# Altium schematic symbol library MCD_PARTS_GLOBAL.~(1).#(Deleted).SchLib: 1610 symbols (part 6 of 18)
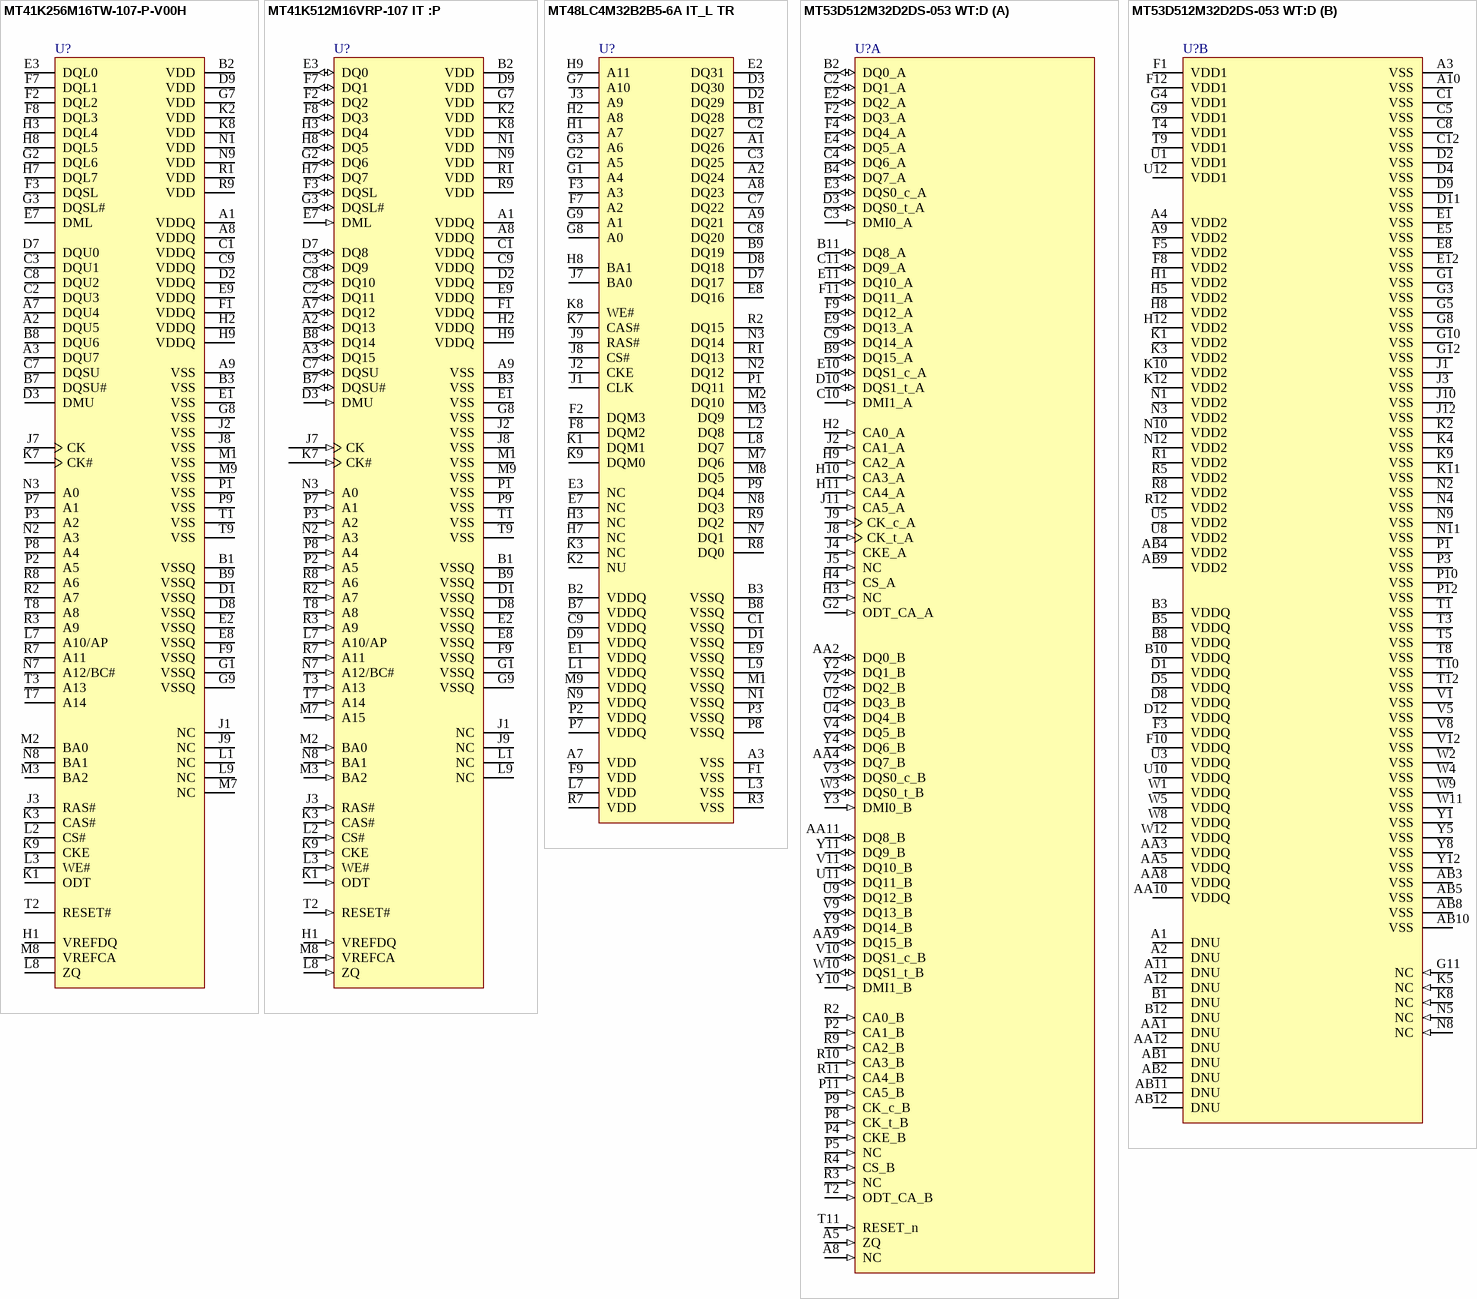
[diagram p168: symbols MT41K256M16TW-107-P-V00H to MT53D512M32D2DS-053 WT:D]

## MT41K512M16VRP-107 IT :P
designator U?
pins: A1 VDDQ "DQ Power Supply: 1.5 V +/- 0.075 V for standard voltage or 1.35V +0.1V, -0.067V for low voltage", A2 DQ13 (io) "Data Input/ Output: Bi-directional data bus.", A3 DQ15 (io) "Data Input/ Output: Bi-directional data bus.", A7 DQ12 (io) "Data Input/ Output: Bi-directional data bus.", A8 VDDQ "DQ Power Supply: 1.5 V +/- 0.075 V for standard voltage or 1.35V +0.1V, -0.067V for low voltage", A9 VSS "Ground", B1 VSSQ "DQ Ground", B2 VDD "Power Supply: 1.5 V +/- 0.075 V for standard voltage or 1.35V +0.1V, -0.067V for low voltage", B3 VSS "Ground", B7 DQSU# (io) "Data Strobe: output with read data, input with write data. Edge-aligned with read data, centered in write data. For the x16, DQSL corresponds to the data on DQL0-DQL7; DQSU corresponds to the data on DQU0-DQU7. The data strobes DQS, DQSL, and DQSU are pa", B8 DQ14 (io) "Data Input/ Output: Bi-directional data bus.", B9 VSSQ "DQ Ground", C1 VDDQ "DQ Power Supply: 1.5 V +/- 0.075 V for standard voltage or 1.35V +0.1V, -0.067V for low voltage", C2 DQ11 (io) "Data Input/ Output: Bi-directional data bus.", C3 DQ9 (io) "Data Input/ Output: Bi-directional data bus.", C7 DQSU (io) "Data Strobe: output with read data, input with write data. Edge-aligned with read data, centered in write data. For the x16, DQSL corresponds to the data on DQL0-DQL7; DQSU corresponds to the data on DQU0-DQU7. The data strobes DQS, DQSL, and DQSU are pa", C8 DQ10 (io) "Data Input/ Output: Bi-directional data bus.", C9 VDDQ "DQ Power Supply: 1.5 V +/- 0.075 V for standard voltage or 1.35V +0.1V, -0.067V for low voltage", D1 VSSQ "DQ Ground", D2 VDDQ "DQ Power Supply: 1.5 V +/- 0.075 V for standard voltage or 1.35V +0.1V, -0.067V for low voltage", D3 DMU (in) "Input Data Mask: DM is an input mask signal for write data. Input data is masked when DM is sampled HIGH coincident with that input data during a Write access. DM is sampled on both edges of DQS. For x8 device, the function of DM or TDQS/TDQS# is enabled", D7 DQ8 (io) "Data Input/ Output: Bi-directional data bus.", D8 VSSQ "DQ Ground", D9 VDD "Power Supply: 1.5 V +/- 0.075 V for standard voltage or 1.35V +0.1V, -0.067V for low voltage", E1 VSS "Ground", E2 VSSQ "DQ Ground", E3 DQ0 (io) "Data Input/ Output: Bi-directional data bus.", E7 DML (in) "Input Data Mask: DM is an input mask signal for write data. Input data is masked when DM is sampled HIGH coincident with that input data during a Write access. DM is sampled on both edges of DQS. For x8 device, the function of DM or TDQS/TDQS# is enabled", E8 VSSQ "DQ Ground", E9 VDDQ "DQ Power Supply: 1.5 V +/- 0.075 V for standard voltage or 1.35V +0.1V, -0.067V for low voltage", F1 VDDQ "DQ Power Supply: 1.5 V +/- 0.075 V for standard voltage or 1.35V +0.1V, -0.067V for low voltage", F2 DQ2 (io) "Data Input/ Output: Bi-directional data bus.", F3 DQSL (io) "Data Strobe: output with read data, input with write data. Edge-aligned with read data, centered in write data. For the x16, DQSL corresponds to the data on DQL0-DQL7; DQSU corresponds to the data on DQU0-DQU7. The data strobes DQS, DQSL, and DQSU are pa", F7 DQ1 (io) "Data Input/ Output: Bi-directional data bus.", F8 DQ3 (io) "Data Input/ Output: Bi-directional data bus.", F9 VSSQ "DQ Ground", G1 VSSQ "DQ Ground", G2 DQ6 (io) "Data Input/ Output: Bi-directional data bus.", G3 DQSL# (io) "Data Strobe: output with read data, input with write data. Edge-aligned with read data, centered in write data. For the x16, DQSL corresponds to the data on DQL0-DQL7; DQSU corresponds to the data on DQU0-DQU7. The data strobes DQS, DQSL, and DQSU are pa", G7 VDD "Power Supply: 1.5 V +/- 0.075 V for standard voltage or 1.35V +0.1V, -0.067V for low voltage", G8 VSS "Ground", G9 VSSQ "DQ Ground", H1 VREFDQ (in) "Reference voltage for DQ", H2 VDDQ "DQ Power Supply: 1.5 V +/- 0.075 V for standard voltage or 1.35V +0.1V, -0.067V for low voltage", H3 DQ4 (io) "Data Input/ Output: Bi-directional data bus.", H7 DQ7 (io) "Data Input/ Output: Bi-directional data bus.", H8 DQ5 (io) "Data Input/ Output: Bi-directional data bus.", H9 VDDQ "DQ Power Supply: 1.5 V +/- 0.075 V for standard voltage or 1.35V +0.1V, -0.067V for low voltage", J1 NC "No Connect: No internal electrical connection is present.", J2 VSS "Ground", J3 RAS# (in) "Command Inputs: RAS#, CAS# and WE# (along with CS#) define the command being entered.", J7 CK (in) "Clock: CK and CK# are differential clock inputs. All address and control input signals are sampled on the crossing of the positive edge of CK and negative edge of CK#.", J8 VSS "Ground", J9 NC "No Connect: No internal electrical connection is present.", K1 ODT (in) "On Die Termination: ODT (registered HIGH) enables termination resistance internal to the DDR3 SDRAM. When enabled, ODT is only applied to each DQ, DQSU, DQSU#, DQSL, DQSL#, DMU, and DML signal. The ODT pin will be ignored if MR1 and MR2 are programmed to", K2 VDD "Power Supply: 1.5 V +/- 0.075 V for standard voltage or 1.35V +0.1V, -0.067V for low voltage", K3 CAS# (in) "Command Inputs: RAS#, CAS# and WE# (along with CS#) define the command being entered.", K7 CK# (in) "Clock: CK and CK# are differential clock inputs. All address and control input signals are sampled on the crossing of the positive edge of CK and negative edge of CK#.", K8 VDD "Power Supply: 1.5 V +/- 0.075 V for standard voltage or 1.35V +0.1V, -0.067V for low voltage", K9 CKE (in) "Clock Enable: CKE HIGH activates, and CKE Low deactivates, internal clock signals and device input buffers and output drivers. Taking CKE Low provides Precharge Power-Down and Self-Refresh operation (all banks idle), or Active Power-Down (row Active in a", L1 NC "No Connect: No internal electrical connection is present.", L2 CS# (in) "Chip Select: All commands are masked when CS# is registered HIGH. CS# provides for external Rank selection on systems with multiple Ranks. CS# is considered part of the command code.", L3 WE# (in) "Command Inputs: RAS#, CAS# and WE# (along with CS#) define the command being entered.", L7 A10/AP (in) "Auto-precharge: A10 is sampled during Read/Write commands to determine whether Autoprecharge should be performed to the accessed bank after the Read/Write operation. (HIGH: Autoprecharge; LOW: no Autoprecharge). A10 is sampled during a Precharge command", L8 ZQ (in) "Reference Pin for ZQ", L9 NC "No Connect: No internal electrical connection is present.", M1 VSS "Ground", M2 BA0 (in) "Bank Address Inputs: BA0 - BA2 define to which bank an Active, Read, Write, or Precharge command is being applied. Bank address also determines which mode register is to be accessed during a MRS cycle.", M3 BA2 (in) "Bank Address Inputs: BA0 - BA2 define to which bank an Active, Read, Write, or Precharge command is being applied. Bank address also determines which mode register is to be accessed during a MRS cycle.", M7 A15 (in) "Address Inputs: Provide the row address for Active commands and the column address for Read/ Write commands to select one location out of the memory array in the respective bank. (A10/AP and A12/BC# have additional functions; see below). The address inpu", M8 VREFCA (in) "Reference voltage for CA", M9 VSS "Ground", N1 VDD "Power Supply: 1.5 V +/- 0.075 V for standard voltage or 1.35V +0.1V, -0.067V for low voltage", N2 A3 (in) "Address Inputs: Provide the row address for Active commands and the column address for Read/ Write commands to select one location out of the memory array in the respective bank. (A10/AP and A12/BC# have additional functions; see below). The address inpu", N3 A0 (in) "Address Inputs: Provide the row address for Active commands and the column address for Read/ Write commands to select one location out of the memory array in the respective bank. (A10/AP and A12/BC# have additional functions; see below). The address inpu", N7 A12/BC# (in) "Burst Chop: A12 / BC# is sampled during Read and Write commands to determine if burst chop (on-the-fly) will be performed. (HIGH, no burst chop; LOW: burst chopped). See command truth table for details.", N8 BA1 (in) "Bank Address Inputs: BA0 - BA2 define to which bank an Active, Read, Write, or Precharge command is being applied. Bank address also determines which mode register is to be accessed during a MRS cycle.", N9 VDD "Power Supply: 1.5 V +/- 0.075 V for standard voltage or 1.35V +0.1V, -0.067V for low voltage", P1 VSS "Ground", P2 A5 (in) "Address Inputs: Provide the row address for Active commands and the column address for Read/ Write commands to select one location out of the memory array in the respective bank. (A10/AP and A12/BC# have additional functions; see below). The address inpu", P3 A2 (in) "Address Inputs: Provide the row address for Active commands and the column address for Read/ Write commands to select one location out of the memory array in the respective bank. (A10/AP and A12/BC# have additional functions; see below). The address inpu", P7 A1 (in) "Address Inputs: Provide the row address for Active commands and the column address for Read/ Write commands to select one location out of the memory array in the respective bank. (A10/AP and A12/BC# have additional functions; see below). The address inpu", P8 A4 (in) "Address Inputs: Provide the row address for Active commands and the column address for Read/ Write commands to select one location out of the memory array in the respective bank. (A10/AP and A12/BC# have additional functions; see below). The address inpu", P9 VSS "Ground", R1 VDD "Power Supply: 1.5 V +/- 0.075 V for standard voltage or 1.35V +0.1V, -0.067V for low voltage", R2 A7 (in) "Address Inputs: Provide the row address for Active commands and the column address for Read/ Write commands to select one location out of the memory array in the respective bank. (A10/AP and A12/BC# have additional functions; see below). The address inpu", R3 A9 (in) "Address Inputs: Provide the row address for Active commands and the column address for Read/ Write commands to select one location out of the memory array in the respective bank. (A10/AP and A12/BC# have additional functions; see below). The address inpu", R7 A11 (in) "Address Inputs: Provide the row address for Active commands and the column address for Read/ Write commands to select one location out of the memory array in the respective bank. (A10/AP and A12/BC# have additional functions; see below). The address inpu", R8 A6 (in) "Address Inputs: Provide the row address for Active commands and the column address for Read/ Write commands to select one location out of the memory array in the respective bank. (A10/AP and A12/BC# have additional functions; see below). The address inpu", R9 VDD "Power Supply: 1.5 V +/- 0.075 V for standard voltage or 1.35V +0.1V, -0.067V for low voltage", T1 VSS "Ground", T2 RESET# (in) "Active Low Asynchronous Reset: Reset is active when RESET# is LOW, and inactive when RESET# is HIGH. RESET# must be HIGH during normal operation. RESET# is a CMOS rail- to-rail signal with DC high and low at 80% and 20% of VDD, i.e., 1.20V for DC high an", T3 A13 (in) "Address Inputs: Provide the row address for Active commands and the column address for Read/ Write commands to select one location out of the memory array in the respective bank. (A10/AP and A12/BC# have additional functions; see below). The address inpu", T7 A14 (in) "Address Inputs: Provide the row address for Active commands and the column address for Read/ Write commands to select one location out of the memory array in the respective bank. (A10/AP and A12/BC# have additional functions; see below). The address inpu", T8 A8 (in) "Address Inputs: Provide the row address for Active commands and the column address for Read/ Write commands to select one location out of the memory array in the respective bank. (A10/AP and A12/BC# have additional functions; see below). The address inpu", T9 VSS "Ground"

## MT48LC4M32B2B5-6A IT_L TR
designator U?
pins: A1 DQ26, A2 DQ24, A3 VSS, A7 VDD, A8 DQ23, A9 DQ21, B1 DQ28, B2 VDDQ, B3 VSSQ, B7 VDDQ, B8 VSSQ, B9 DQ19, C1 VSSQ, C2 DQ27, C3 DQ25, C7 DQ22, C8 DQ20, C9 VDDQ, D1 VSSQ, D2 DQ29, D3 DQ30, D7 DQ17, D8 DQ18, D9 VDDQ, E1 VDDQ, E2 DQ31, E3 NC, E7 NC, E8 DQ16, E9 VSSQ, F1 VSS, F2 DQM3, F3 A3, F7 A2, F8 DQM2, F9 VDD, G1 A4, G2 A5, G3 A6, G7 A10, G8 A0, G9 A1, H1 A7, H2 A8, H3 NC, H7 NC, H8 BA1, H9 A11, J1 CLK, J2 CKE, J3 A9, J7 BA0, J8 CS#, J9 RAS#, K1 DQM1, K2 NU, K3 NC, K7 CAS#, K8 WE#, K9 DQM0, L1 VDDQ, L2 DQ8, L3 VSS, L7 VDD, L8 DQ7, L9 VSSQ, M1 VSSQ, M2 DQ10, M3 DQ9, M7 DQ6, M8 DQ5, M9 VDDQ, N1 VSSQ, N2 DQ12, N3 DQ14, N7 DQ1, N8 DQ3, N9 VDDQ, P1 DQ11, P2 VDDQ, P3 VSSQ, P7 VDDQ, P8 VSSQ, P9 DQ4, R1 DQ13, R2 DQ15, R3 VSS, R7 VDD, R8 DQ0, R9 DQ2

## MT53D512M32D2DS-053 WT:D
designator U?
part A pins: A5 ZQ (in) "External impedance (240 ohm): This signal is used to calibrate the device output impedance.", A8 NC (in), AA2 DQ0_B (io) "Data input/output: Bidirectional data bus.", AA4 DQ7_B (io) "Data input/output: Bidirectional data bus.", AA9 DQ15_B (io) "Data input/output: Bidirectional data bus.", AA11 DQ8_B (io) "Data input/output: Bidirectional data bus.", B2 DQ0_A (io) "Data input/output: Bidirectional data bus.", B4 DQ7_A (io) "Data input/output: Bidirectional data bus.", B9 DQ15_A (io) "Data input/output: Bidirectional data bus.", B11 DQ8_A (io) "Data input/output: Bidirectional data bus.", C2 DQ1_A (io) "Data input/output: Bidirectional data bus.", C3 DMI0_A (in) "Input data mask: DM is an input mask signal for write data. Although DM ballsare input-only, the DM loading is designed to match that of DQ and DQS balls.DM[3:0] is DM for each of the four data bytes, respectively.", C4 DQ6_A (io) "Data input/output: Bidirectional data bus.", C9 DQ14_A (io) "Data input/output: Bidirectional data bus.", C10 DMI1_A (in) "Input data mask: DM is an input mask signal for write data. Although DM ballsare input-only, the DM loading is designed to match that of DQ and DQS balls.DM[3:0] is DM for each of the four data bytes, respectively.", C11 DQ9_A (io) "Data input/output: Bidirectional data bus.", D3 DQS0_t_A (io) "Data strobe: The data strobe is bidirectional (used for read and write data) andcomplementary (DQS and DQS#). It is edge-aligned output with read data andcentered input with write data. DQS[3:0]/DQS[3:0]# is DQS for each of (See Datasheet)", D10 DQS1_t_A (io) "Data strobe: The data strobe is bidirectional (used for read and write data) andcomplementary (DQS and DQS#). It is edge-aligned output with read data andcentered input with write data. DQS[3:0]/DQS[3:0]# is DQS for each of (See Datasheet)", E2 DQ2_A (io) "Data input/output: Bidirectional data bus.", E3 DQS0_c_A (io) "Data strobe: The data strobe is bidirectional (used for read and write data) andcomplementary (DQS and DQS#). It is edge-aligned output with read data andcentered input with write data. DQS[3:0]/DQS[3:0]# is DQS for each of (See Datasheet)", E4 DQ5_A (io) "Data input/output: Bidirectional data bus.", E9 DQ13_A (io) "Data input/output: Bidirectional data bus.", E10 DQS1_c_A (io) "Data strobe: The data strobe is bidirectional (used for read and write data) andcomplementary (DQS and DQS#). It is edge-aligned output with read data andcentered input with write data. DQS[3:0]/DQS[3:0]# is DQS for each of (See Datasheet)", E11 DQ10_A (io) "Data input/output: Bidirectional data bus.", F2 DQ3_A (io) "Data input/output: Bidirectional data bus.", F4 DQ4_A (io) "Data input/output: Bidirectional data bus.", F9 DQ12_A (io) "Data input/output: Bidirectional data bus.", F11 DQ11_A (io) "Data input/output: Bidirectional data bus.", G2 ODT_CA_A (in) "on die termination on CA", H2 CA0_A (in) "Command/address inputs: Provide the command and address inputs accordingto the command truth table.", H3 NC (in), H4 CS_A (in) "Chip select: CS# is considered part of the command code and is sampled at therising edge of CK.", H9 CA2_A (in) "Command/address inputs: Provide the command and address inputs accordingto the command truth table.", H10 CA3_A (in) "Command/address inputs: Provide the command and address inputs accordingto the command truth table.", H11 CA4_A (in) "Command/address inputs: Provide the command and address inputs accordingto the command truth table.", J2 CA1_A (in) "Command/address inputs: Provide the command and address inputs accordingto the command truth table.", J4 CKE_A (in) "Clock enable: CKE HIGH activates and CKE LOW deactivates the internal clocksignals, input buffers, and output drivers. Power-saving modes are entered andexited via CKE transitions. CKE is considered part of the command code. (See Datasheet)", J5 NC (in), J8 CK_t_A (in) "Clock: CK and CK# are differential clock inputs. All CA inputs are sampled onboth rising and falling edges of CK. CS and CKE inputs are sampled at the risingedge of CK. AC timings are referenced to clock.", J9 CK_c_A (in) "Clock: CK and CK# are differential clock inputs. All CA inputs are sampled onboth rising and falling edges of CK. CS and CKE inputs are sampled at the risingedge of CK. AC timings are referenced to clock.", J11 CA5_A (in) "Command/address inputs: Provide the command and address inputs accordingto the command truth table.", P2 CA1_B (in) "Command/address inputs: Provide the command and address inputs accordingto the command truth table.", P4 CKE_B (in) "Clock enable: CKE HIGH activates and CKE LOW deactivates the internal clocksignals, input buffers, and output drivers. Power-saving modes are entered andexited via CKE transitions. CKE is considered part of the command code. (See Datasheet)", P5 NC (in), P8 CK_t_B (in) "Clock: CK and CK# are differential clock inputs. All CA inputs are sampled onboth rising and falling edges of CK. CS and CKE inputs are sampled at the risingedge of CK. AC timings are referenced to clock.", P9 CK_c_B (in) "Clock: CK and CK# are differential clock inputs. All CA inputs are sampled onboth rising and falling edges of CK. CS and CKE inputs are sampled at the risingedge of CK. AC timings are referenced to clock.", P11 CA5_B (in) "Command/address inputs: Provide the command and address inputs accordingto the command truth table.", R2 CA0_B (in) "Command/address inputs: Provide the command and address inputs accordingto the command truth table.", R3 NC (in), R4 CS_B (in) "Chip select: CS# is considered part of the command code and is sampled at therising edge of CK.", R9 CA2_B (in) "Command/address inputs: Provide the command and address inputs accordingto the command truth table.", R10 CA3_B (in) "Command/address inputs: Provide the command and address inputs accordingto the command truth table.", R11 CA4_B (in) "Command/address inputs: Provide the command and address inputs accordingto the command truth table.", T2 ODT_CA_B (in) "on die termination on CA", T11 RESET_n (in) "Reset active low", U2 DQ3_B (io) "Data input/output: Bidirectional data bus.", U4 DQ4_B (io) "Data input/output: Bidirectional data bus.", U9 DQ12_B (io) "Data input/output: Bidirectional data bus.", U11 DQ11_B (io) "Data input/output: Bidirectional data bus.", V2 DQ2_B (io) "Data input/output: Bidirectional data bus.", V3 DQS0_c_B (io) "Data strobe: The data strobe is bidirectional (used for read and write data) andcomplementary (DQS and DQS#). It is edge-aligned output with read data andcentered input with write data. DQS[3:0]/DQS[3:0]# is DQS for each of (See Datasheet)", V4 DQ5_B (io) "Data input/output: Bidirectional data bus.", V9 DQ13_B (io) "Data input/output: Bidirectional data bus.", V10 DQS1_c_B (io) "Data strobe: The data strobe is bidirectional (used for read and write data) andcomplementary (DQS and DQS#). It is edge-aligned output with read data andcentered input with write data. DQS[3:0]/DQS[3:0]# is DQS for each of (See Datasheet)", V11 DQ10_B (io) "Data input/output: Bidirectional data bus.", W3 DQS0_t_B (io) "Data strobe: The data strobe is bidirectional (used for read and write data) andcomplementary (DQS and DQS#). It is edge-aligned output with read data andcentered input with write data. DQS[3:0]/DQS[3:0]# is DQS for each of (See Datasheet)", W10 DQS1_t_B (io) "Data strobe: The data strobe is bidirectional (used for read and write data) andcomplementary (DQS and DQS#). It is edge-aligned output with read data andcentered input with write data. DQS[3:0]/DQS[3:0]# is DQS for each of (See Datasheet)", Y2 DQ1_B (io) "Data input/output: Bidirectional data bus.", Y3 DMI0_B (in) "Input data mask: DM is an input mask signal for write data. Although DM ballsare input-only, the DM loading is designed to match that of DQ and DQS balls.DM[3:0] is DM for each of the four data bytes, respectively.", Y4 DQ6_B (io) "Data input/output: Bidirectional data bus.", Y9 DQ14_B (io) "Data input/output: Bidirectional data bus.", Y10 DMI1_B (in) "Input data mask: DM is an input mask signal for write data. Although DM ballsare input-only, the DM loading is designed to match that of DQ and DQS balls.DM[3:0] is DM for each of the four data bytes, respectively.", Y11 DQ9_B (io) "Data input/output: Bidirectional data bus."
part B pins: A1 DNU "Do not use: Must be grounded or left floating.", A2 DNU "Do not use: Must be grounded or left floating.", A3 VSS (power) "Common ground.", A4 VDD2 (power) "Core power: Supply 2.", A9 VDD2 (power) "Core power: Supply 2.", A10 VSS (power) "Common ground.", A11 DNU "Do not use: Must be grounded or left floating.", A12 DNU "Do not use: Must be grounded or left floating.", AA1 DNU "Do not use: Must be grounded or left floating.", AA3 VDDQ (power) "DQ power supply: Isolated on the die for improved noise immunity.", AA5 VDDQ (power) "DQ power supply: Isolated on the die for improved noise immunity.", AA8 VDDQ (power) "DQ power supply: Isolated on the die for improved noise immunity.", AA10 VDDQ (power) "DQ power supply: Isolated on the die for improved noise immunity.", AA12 DNU "Do not use: Must be grounded or left floating.", AB1 DNU "Do not use: Must be grounded or left floating.", AB2 DNU "Do not use: Must be grounded or left floating.", AB3 VSS "Common ground.", AB4 VDD2 (power) "Core power: Supply 2.", AB5 VSS "Common ground.", AB8 VSS "Common ground.", AB9 VDD2 (power) "Core power: Supply 2.", AB10 VSS "Common ground.", AB11 DNU "Do not use: Must be grounded or left floating.", AB12 DNU "Do not use: Must be grounded or left floating.", B1 DNU "Do not use: Must be grounded or left floating.", B3 VDDQ (power) "DQ power supply: Isolated on the die for improved noise immunity.", B5 VDDQ (power) "DQ power supply: Isolated on the die for improved noise immunity.", B8 VDDQ (power) "DQ power supply: Isolated on the die for improved noise immunity.", B10 VDDQ (power) "DQ power supply: Isolated on the die for improved noise immunity.", B12 DNU "Do not use: Must be grounded or left floating.", C1 VSS (power) "Common ground.", C5 VSS (power) "Common ground.", C8 VSS (power) "Common ground.", C12 VSS (power) "Common ground.", D1 VDDQ (power) "DQ power supply: Isolated on the die for improved noise immunity.", D2 VSS (power) "Common ground.", D4 VSS (power) "Common ground.", D5 VDDQ (power) "DQ power supply: Isolated on the die for improved noise immunity.", D8 VDDQ (power) "DQ power supply: Isolated on the die for improved noise immunity.", D9 VSS (power) "Common ground.", D11 VSS (power) "Common ground.", D12 VDDQ (power) "DQ power supply: Isolated on the die for improved noise immunity.", E1 VSS (power) "Common ground.", E5 VSS (power) "Common ground.", E8 VSS (power) "Common ground.", E12 VSS (power) "Common ground.", F1 VDD1 (power) "Core power: Supply 1.", F3 VDDQ (power) "DQ power supply: Isolated on the die for improved noise immunity.", F5 VDD2 (power) "Core power: Supply 2.", F8 VDD2 (power) "Core power: Supply 2.", F10 VDDQ (power) "DQ power supply: Isolated on the die for improved noise immunity.", F12 VDD1 (power) "Core power: Supply 1.", G1 VSS (power) "Common ground.", G3 VSS (power) "Common ground.", G4 VDD1 (power) "Core power: Supply 1.", G5 VSS (power) "Common ground.", G8 VSS (power) "Common ground.", G9 VDD1 (power) "Core power: Supply 1.", G10 VSS (power) "Common ground.", G11 NC (in) "Not connected", G12 VSS (power) "Common ground.", H1 VDD2 (power) "Core power: Supply 2.", H5 VDD2 (power) "Core power: Supply 2.", H8 VDD2 (power) "Core power: Supply 2.", H12 VDD2 (power) "Core power: Supply 2.", J1 VSS (power) "Common ground.", J3 VSS (power) "Common ground.", J10 VSS (power) "Common ground.", J12 VSS (power) "Common ground.", K1 VDD2 (power) "Core power: Supply 2.", K2 VSS (power) "Common ground.", K3 VDD2 (power) "Core power: Supply 2.", K4 VSS (power) "Common ground.", K5 NC (in) "Not connected", K8 NC (in) "Not connected", K9 VSS (power) "Common ground.", K10 VDD2 (power) "Core power: Supply 2.", K11 VSS "Common ground.", K12 VDD2 (power) "Core power: Supply 2.", N1 VDD2 (power) "Core power: Supply 2.", N2 VSS "Common ground.", N3 VDD2 (power) "Core power: Supply 2.", N4 VSS "Common ground.", N5 NC (in) "Not connected", N8 NC (in) "Not connected", N9 VSS "Common ground.", N10 VDD2 (power) "Core power: Supply 2.", N11 VSS "Common ground.", N12 VDD2 (power) "Core power: Supply 2.", P1 VSS "Common ground.", P3 VSS (power) "Common ground.", P10 VSS (power) "Common ground.", P12 VSS "Common ground.", R1 VDD2 (power) "Core power: Supply 2.", R5 VDD2 (power) "Core power: Supply 2.", R8 VDD2 (power) "Core power: Supply 2.", R12 VDD2 (power) "Core power: Supply 2.", T1 VSS "Common ground.", T3 VSS "Common ground.", T4 VDD1 (power) "Core power: Supply 1.", T5 VSS "Common ground.", T8 VSS "Common ground.", T9 VDD1 (power) "Core power: Supply 1.", T10 VSS "Common ground.", T12 VSS "Common ground.", U1 VDD1 (power) "Core power: Supply 1.", U3 VDDQ (power) "DQ power supply: Isolated on the die for improved noise immunity.", U5 VDD2 (power) "Core power: Supply 2.", U8 VDD2 (power) "Core power: Supply 2.", U10 VDDQ (power) "DQ power supply: Isolated on the die for improved noise immunity.", U12 VDD1 (power) "Core power: Supply 1.", V1 VSS (power) "Common ground.", V5 VSS (power) "Common ground.", V8 VSS "Common ground.", V12 VSS "Common ground.", W1 VDDQ (power) "DQ power supply: Isolated on the die for improved noise immunity.", W2 VSS "Common ground.", W4 VSS "Common ground.", W5 VDDQ (power) "DQ power supply: Isolated on the die for improved noise immunity.", W8 VDDQ (power) "DQ power supply: Isolated on the die for improved noise immunity.", W9 VSS "Common ground.", W11 VSS "Common ground.", W12 VDDQ (power) "DQ power supply: Isolated on the die for improved noise immunity.", Y1 VSS "Common ground.", Y5 VSS "Common ground.", Y8 VSS "Common ground.", Y12 VSS "Common ground."

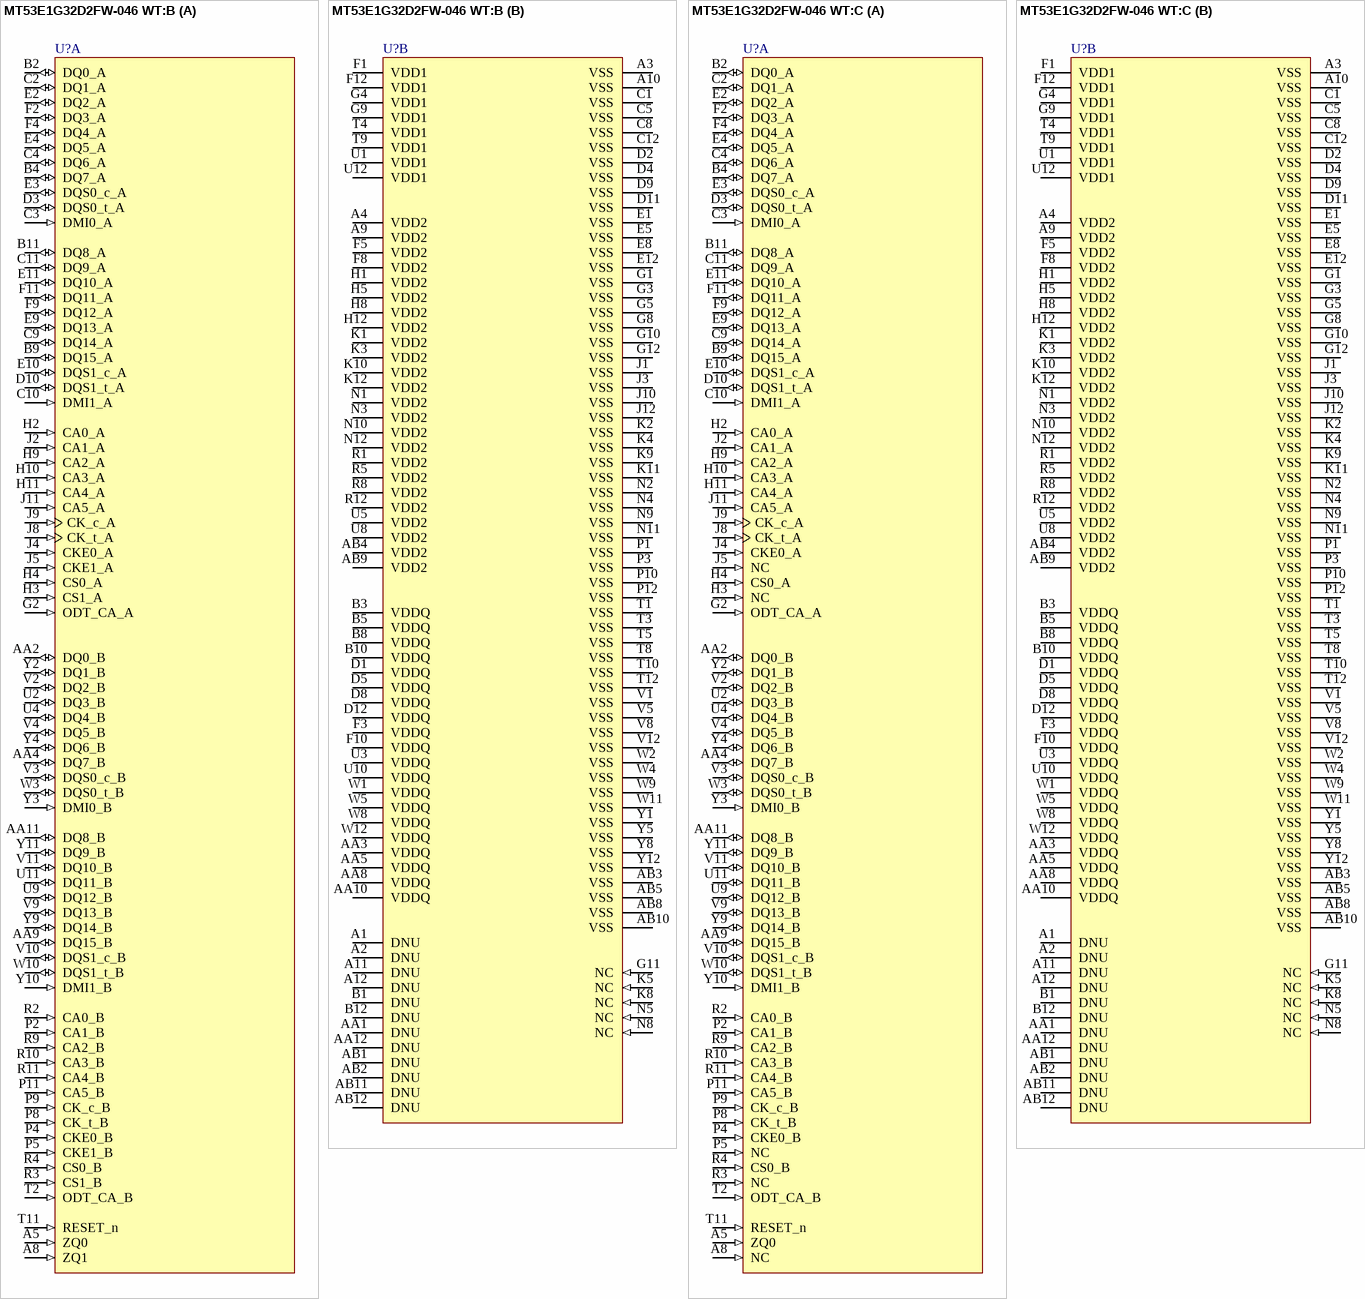
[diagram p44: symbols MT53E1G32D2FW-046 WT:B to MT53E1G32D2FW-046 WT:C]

## MT53E1G32D2FW-046 WT:B
designator U?
part A pins: A5 ZQ0 (in) "External impedance (240 ohm): This signal is used to calibrate the device output impedance.", A8 ZQ1 (in) "NC", AA2 DQ0_B (io) "Data input/output: Bidirectional data bus.", AA4 DQ7_B (io) "Data input/output: Bidirectional data bus.", AA9 DQ15_B (io) "Data input/output: Bidirectional data bus.", AA11 DQ8_B (io) "Data input/output: Bidirectional data bus.", B2 DQ0_A (io) "Data input/output: Bidirectional data bus.", B4 DQ7_A (io) "Data input/output: Bidirectional data bus.", B9 DQ15_A (io) "Data input/output: Bidirectional data bus.", B11 DQ8_A (io) "Data input/output: Bidirectional data bus.", C2 DQ1_A (io) "Data input/output: Bidirectional data bus.", C3 DMI0_A (in) "Input data mask: DM is an input mask signal for write data. Although DM ballsare input-only, the DM loading is designed to match that of DQ and DQS balls.DM[3:0] is DM for each of the four data bytes, respectively.", C4 DQ6_A (io) "Data input/output: Bidirectional data bus.", C9 DQ14_A (io) "Data input/output: Bidirectional data bus.", C10 DMI1_A (in) "Input data mask: DM is an input mask signal for write data. Although DM ballsare input-only, the DM loading is designed to match that of DQ and DQS balls.DM[3:0] is DM for each of the four data bytes, respectively.", C11 DQ9_A (io) "Data input/output: Bidirectional data bus.", D3 DQS0_t_A (io) "Data strobe: The data strobe is bidirectional (used for read and write data) andcomplementary (DQS and DQS#). It is edge-aligned output with read data andcentered input with write data. DQS[3:0]/DQS[3:0]# is DQS for each of (See Datasheet)", D10 DQS1_t_A (io) "Data strobe: The data strobe is bidirectional (used for read and write data) andcomplementary (DQS and DQS#). It is edge-aligned output with read data andcentered input with write data. DQS[3:0]/DQS[3:0]# is DQS for each of (See Datasheet)", E2 DQ2_A (io) "Data input/output: Bidirectional data bus.", E3 DQS0_c_A (io) "Data strobe: The data strobe is bidirectional (used for read and write data) andcomplementary (DQS and DQS#). It is edge-aligned output with read data andcentered input with write data. DQS[3:0]/DQS[3:0]# is DQS for each of (See Datasheet)", E4 DQ5_A (io) "Data input/output: Bidirectional data bus.", E9 DQ13_A (io) "Data input/output: Bidirectional data bus.", E10 DQS1_c_A (io) "Data strobe: The data strobe is bidirectional (used for read and write data) andcomplementary (DQS and DQS#). It is edge-aligned output with read data andcentered input with write data. DQS[3:0]/DQS[3:0]# is DQS for each of (See Datasheet)", E11 DQ10_A (io) "Data input/output: Bidirectional data bus.", F2 DQ3_A (io) "Data input/output: Bidirectional data bus.", F4 DQ4_A (io) "Data input/output: Bidirectional data bus.", F9 DQ12_A (io) "Data input/output: Bidirectional data bus.", F11 DQ11_A (io) "Data input/output: Bidirectional data bus.", G2 ODT_CA_A (in) "on die termination on CA", H2 CA0_A (in) "Command/address inputs: Provide the command and address inputs accordingto the command truth table.", H3 CS1_A (in) "NC", H4 CS0_A (in) "Chip select: CS# is considered part of the command code and is sampled at therising edge of CK.", H9 CA2_A (in) "Command/address inputs: Provide the command and address inputs accordingto the command truth table.", H10 CA3_A (in) "Command/address inputs: Provide the command and address inputs accordingto the command truth table.", H11 CA4_A (in) "Command/address inputs: Provide the command and address inputs accordingto the command truth table.", J2 CA1_A (in) "Command/address inputs: Provide the command and address inputs accordingto the command truth table.", J4 CKE0_A (in) "Clock enable: CKE HIGH activates and CKE LOW deactivates the internal clocksignals, input buffers, and output drivers. Power-saving modes are entered andexited via CKE transitions. CKE is considered part of the command code. (See Datasheet)", J5 CKE1_A (in) "NC", J8 CK_t_A (in) "Clock: CK and CK# are differential clock inputs. All CA inputs are sampled onboth rising and falling edges of CK. CS and CKE inputs are sampled at the risingedge of CK. AC timings are referenced to clock.", J9 CK_c_A (in) "Clock: CK and CK# are differential clock inputs. All CA inputs are sampled onboth rising and falling edges of CK. CS and CKE inputs are sampled at the risingedge of CK. AC timings are referenced to clock.", J11 CA5_A (in) "Command/address inputs: Provide the command and address inputs accordingto the command truth table.", P2 CA1_B (in) "Command/address inputs: Provide the command and address inputs accordingto the command truth table.", P4 CKE0_B (in) "Clock enable: CKE HIGH activates and CKE LOW deactivates the internal clocksignals, input buffers, and output drivers. Power-saving modes are entered andexited via CKE transitions. CKE is considered part of the command code. (See Datasheet)", P5 CKE1_B (in) "NC", P8 CK_t_B (in) "Clock: CK and CK# are differential clock inputs. All CA inputs are sampled onboth rising and falling edges of CK. CS and CKE inputs are sampled at the risingedge of CK. AC timings are referenced to clock.", P9 CK_c_B (in) "Clock: CK and CK# are differential clock inputs. All CA inputs are sampled onboth rising and falling edges of CK. CS and CKE inputs are sampled at the risingedge of CK. AC timings are referenced to clock.", P11 CA5_B (in) "Command/address inputs: Provide the command and address inputs accordingto the command truth table.", R2 CA0_B (in) "Command/address inputs: Provide the command and address inputs accordingto the command truth table.", R3 CS1_B (in) "NC", R4 CS0_B (in) "Chip select: CS# is considered part of the command code and is sampled at therising edge of CK.", R9 CA2_B (in) "Command/address inputs: Provide the command and address inputs accordingto the command truth table.", R10 CA3_B (in) "Command/address inputs: Provide the command and address inputs accordingto the command truth table.", R11 CA4_B (in) "Command/address inputs: Provide the command and address inputs accordingto the command truth table.", T2 ODT_CA_B (in) "on die termination on CA", T11 RESET_n (in) "Reset active low", U2 DQ3_B (io) "Data input/output: Bidirectional data bus.", U4 DQ4_B (io) "Data input/output: Bidirectional data bus.", U9 DQ12_B (io) "Data input/output: Bidirectional data bus.", U11 DQ11_B (io) "Data input/output: Bidirectional data bus.", V2 DQ2_B (io) "Data input/output: Bidirectional data bus.", V3 DQS0_c_B (io) "Data strobe: The data strobe is bidirectional (used for read and write data) andcomplementary (DQS and DQS#). It is edge-aligned output with read data andcentered input with write data. DQS[3:0]/DQS[3:0]# is DQS for each of (See Datasheet)", V4 DQ5_B (io) "Data input/output: Bidirectional data bus.", V9 DQ13_B (io) "Data input/output: Bidirectional data bus.", V10 DQS1_c_B (io) "Data strobe: The data strobe is bidirectional (used for read and write data) andcomplementary (DQS and DQS#). It is edge-aligned output with read data andcentered input with write data. DQS[3:0]/DQS[3:0]# is DQS for each of (See Datasheet)", V11 DQ10_B (io) "Data input/output: Bidirectional data bus.", W3 DQS0_t_B (io) "Data strobe: The data strobe is bidirectional (used for read and write data) andcomplementary (DQS and DQS#). It is edge-aligned output with read data andcentered input with write data. DQS[3:0]/DQS[3:0]# is DQS for each of (See Datasheet)", W10 DQS1_t_B (io) "Data strobe: The data strobe is bidirectional (used for read and write data) andcomplementary (DQS and DQS#). It is edge-aligned output with read data andcentered input with write data. DQS[3:0]/DQS[3:0]# is DQS for each of (See Datasheet)", Y2 DQ1_B (io) "Data input/output: Bidirectional data bus.", Y3 DMI0_B (in) "Input data mask: DM is an input mask signal for write data. Although DM ballsare input-only, the DM loading is designed to match that of DQ and DQS balls.DM[3:0] is DM for each of the four data bytes, respectively.", Y4 DQ6_B (io) "Data input/output: Bidirectional data bus.", Y9 DQ14_B (io) "Data input/output: Bidirectional data bus.", Y10 DMI1_B (in) "Input data mask: DM is an input mask signal for write data. Although DM ballsare input-only, the DM loading is designed to match that of DQ and DQS balls.DM[3:0] is DM for each of the four data bytes, respectively.", Y11 DQ9_B (io) "Data input/output: Bidirectional data bus."
part B pins: A1 DNU "Do not use: Must be grounded or left floating.", A2 DNU "Do not use: Must be grounded or left floating.", A3 VSS (power) "Common ground.", A4 VDD2 (power) "Core power: Supply 2.", A9 VDD2 (power) "Core power: Supply 2.", A10 VSS (power) "Common ground.", A11 DNU "Do not use: Must be grounded or left floating.", A12 DNU "Do not use: Must be grounded or left floating.", AA1 DNU "Do not use: Must be grounded or left floating.", AA3 VDDQ (power) "DQ power supply: Isolated on the die for improved noise immunity.", AA5 VDDQ (power) "DQ power supply: Isolated on the die for improved noise immunity.", AA8 VDDQ (power) "DQ power supply: Isolated on the die for improved noise immunity.", AA10 VDDQ (power) "DQ power supply: Isolated on the die for improved noise immunity.", AA12 DNU "Do not use: Must be grounded or left floating.", AB1 DNU "Do not use: Must be grounded or left floating.", AB2 DNU "Do not use: Must be grounded or left floating.", AB3 VSS "Common ground.", AB4 VDD2 (power) "Core power: Supply 2.", AB5 VSS "Common ground.", AB8 VSS "Common ground.", AB9 VDD2 (power) "Core power: Supply 2.", AB10 VSS "Common ground.", AB11 DNU "Do not use: Must be grounded or left floating.", AB12 DNU "Do not use: Must be grounded or left floating.", B1 DNU "Do not use: Must be grounded or left floating.", B3 VDDQ (power) "DQ power supply: Isolated on the die for improved noise immunity.", B5 VDDQ (power) "DQ power supply: Isolated on the die for improved noise immunity.", B8 VDDQ (power) "DQ power supply: Isolated on the die for improved noise immunity.", B10 VDDQ (power) "DQ power supply: Isolated on the die for improved noise immunity.", B12 DNU "Do not use: Must be grounded or left floating.", C1 VSS (power) "Common ground.", C5 VSS (power) "Common ground.", C8 VSS (power) "Common ground.", C12 VSS (power) "Common ground.", D1 VDDQ (power) "DQ power supply: Isolated on the die for improved noise immunity.", D2 VSS (power) "Common ground.", D4 VSS (power) "Common ground.", D5 VDDQ (power) "DQ power supply: Isolated on the die for improved noise immunity.", D8 VDDQ (power) "DQ power supply: Isolated on the die for improved noise immunity.", D9 VSS (power) "Common ground.", D11 VSS (power) "Common ground.", D12 VDDQ (power) "DQ power supply: Isolated on the die for improved noise immunity.", E1 VSS (power) "Common ground.", E5 VSS (power) "Common ground.", E8 VSS (power) "Common ground.", E12 VSS (power) "Common ground.", F1 VDD1 (power) "Core power: Supply 1.", F3 VDDQ (power) "DQ power supply: Isolated on the die for improved noise immunity.", F5 VDD2 (power) "Core power: Supply 2.", F8 VDD2 (power) "Core power: Supply 2.", F10 VDDQ (power) "DQ power supply: Isolated on the die for improved noise immunity.", F12 VDD1 (power) "Core power: Supply 1.", G1 VSS (power) "Common ground.", G3 VSS (power) "Common ground.", G4 VDD1 (power) "Core power: Supply 1.", G5 VSS (power) "Common ground.", G8 VSS (power) "Common ground.", G9 VDD1 (power) "Core power: Supply 1.", G10 VSS (power) "Common ground.", G11 NC (in) "Not connected", G12 VSS (power) "Common ground.", H1 VDD2 (power) "Core power: Supply 2.", H5 VDD2 (power) "Core power: Supply 2.", H8 VDD2 (power) "Core power: Supply 2.", H12 VDD2 (power) "Core power: Supply 2.", J1 VSS (power) "Common ground.", J3 VSS (power) "Common ground.", J10 VSS (power) "Common ground.", J12 VSS (power) "Common ground.", K1 VDD2 (power) "Core power: Supply 2.", K2 VSS (power) "Common ground.", K3 VDD2 (power) "Core power: Supply 2.", K4 VSS (power) "Common ground.", K5 NC (in) "Not connected", K8 NC (in) "Not connected", K9 VSS (power) "Common ground.", K10 VDD2 (power) "Core power: Supply 2.", K11 VSS "Common ground.", K12 VDD2 (power) "Core power: Supply 2.", N1 VDD2 (power) "Core power: Supply 2.", N2 VSS "Common ground.", N3 VDD2 (power) "Core power: Supply 2.", N4 VSS "Common ground.", N5 NC (in) "Not connected", N8 NC (in) "Not connected", N9 VSS "Common ground.", N10 VDD2 (power) "Core power: Supply 2.", N11 VSS "Common ground.", N12 VDD2 (power) "Core power: Supply 2.", P1 VSS "Common ground.", P3 VSS (power) "Common ground.", P10 VSS (power) "Common ground.", P12 VSS "Common ground.", R1 VDD2 (power) "Core power: Supply 2.", R5 VDD2 (power) "Core power: Supply 2.", R8 VDD2 (power) "Core power: Supply 2.", R12 VDD2 (power) "Core power: Supply 2.", T1 VSS "Common ground.", T3 VSS "Common ground.", T4 VDD1 (power) "Core power: Supply 1.", T5 VSS "Common ground.", T8 VSS "Common ground.", T9 VDD1 (power) "Core power: Supply 1.", T10 VSS "Common ground.", T12 VSS "Common ground.", U1 VDD1 (power) "Core power: Supply 1.", U3 VDDQ (power) "DQ power supply: Isolated on the die for improved noise immunity.", U5 VDD2 (power) "Core power: Supply 2.", U8 VDD2 (power) "Core power: Supply 2.", U10 VDDQ (power) "DQ power supply: Isolated on the die for improved noise immunity.", U12 VDD1 (power) "Core power: Supply 1.", V1 VSS (power) "Common ground.", V5 VSS (power) "Common ground.", V8 VSS "Common ground.", V12 VSS "Common ground.", W1 VDDQ (power) "DQ power supply: Isolated on the die for improved noise immunity.", W2 VSS "Common ground.", W4 VSS "Common ground.", W5 VDDQ (power) "DQ power supply: Isolated on the die for improved noise immunity.", W8 VDDQ (power) "DQ power supply: Isolated on the die for improved noise immunity.", W9 VSS "Common ground.", W11 VSS "Common ground.", W12 VDDQ (power) "DQ power supply: Isolated on the die for improved noise immunity.", Y1 VSS "Common ground.", Y5 VSS "Common ground.", Y8 VSS "Common ground.", Y12 VSS "Common ground."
